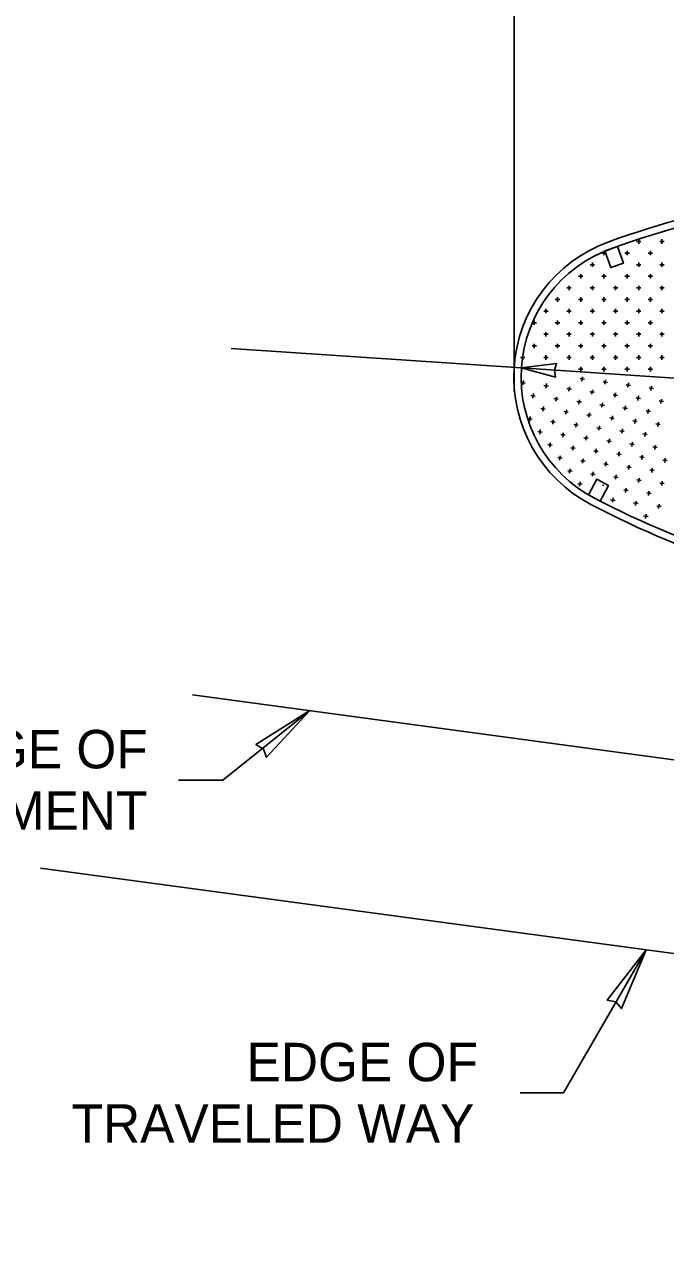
# Model space of a CAD drawing. Extents: x 1312564.5 to 1312581.5, y 1207298.4 to 1207309.4.
# Drawn here: x 1312575.116 to 1312576.451, y 1207303.021 to 1207305.558 of the extents above; entities that cross this region are included whole.
import ezdxf

# ---------------------------------------------------------------- set-up
doc = ezdxf.new("R2010")
doc.units = 0
for name, color, linetype in [('Level 15', 7, 'Continuous'), ('Level 2', 7, 'Continuous'), ('Level 20', 7, 'Continuous'), ('Level 3', 7, 'Continuous'), ('Level 4', 7, 'Continuous'), ('Level 44', 7, 'Continuous')]:
    doc.layers.add(name, color=color, linetype=linetype)

msp = doc.modelspace()

# ---------------------------------------------------------------- linework, layer by layer
at = {"layer": 'Level 15'}
for p, q in [((1312576.1506, 1207304.8426), (1312575.5468, 1207304.8833)), ((1312575.7104, 1207304.129), (1312575.5295, 1207303.9844)), ((1312575.5295, 1207303.9844), (1312575.4373, 1207303.9844)), ((1312576.4101, 1207303.6311), (1312576.2382, 1207303.3333)), ((1312576.2382, 1207303.3333), (1312576.1482, 1207303.3333))]:
    msp.add_line(p, q, dxfattribs=at)
for points in [[(1312576.1354, 1207304.7936), (1312576.1354, 1207306.1548)], [(1312576.1506, 1207304.8426), (1312579.498, 1207304.617)]]:
    msp.add_lwpolyline(points, dxfattribs=at)
for points in [[(1312576.1506, 1207304.8426), (1312576.2239, 1207304.8519), (1312576.2196, 1207304.838), (1312576.222, 1207304.8236)], [(1312575.7104, 1207304.129), (1312575.5982, 1207304.0583), (1312575.6139, 1207304.049), (1312575.6202, 1207304.0319)], [(1312576.4101, 1207303.6311), (1312576.3592, 1207303.5086), (1312576.3474, 1207303.5225), (1312576.3295, 1207303.5258)]]:
    msp.add_lwpolyline(points, close=True, dxfattribs=at)
at = {"layer": 'Level 2'}
for points in [[(1312576.3246, 1207305.0861), (1312576.3506, 1207305.0955), (1312576.3631, 1207305.0608), (1312576.3371, 1207305.0514)], [(1312576.2903, 1207304.578), (1312576.3148, 1207304.5652), (1312576.3319, 1207304.5978), (1312576.3074, 1207304.6106)]]:
    msp.add_lwpolyline(points, close=True, dxfattribs=at)
for centre, radius, start, end in [((1312577.0032, 1207303.2505), 1.9722, 89.8014, 109.8833), ((1312577.0032, 1207303.2505), 1.957, 89.83, 109.8833), ((1312576.4343, 1207304.8235), 0.2995, 109.8833, 176.1437), ((1312576.4343, 1207304.8235), 0.2843, 109.8833, 176.1437), ((1312576.4343, 1207304.8235), 0.2995, 176.1437, 242.4041), ((1312576.4343, 1207304.8235), 0.2843, 176.1437, 242.4041), ((1312577.2091, 1207306.3059), 1.9722, 242.4041, 262.486), ((1312577.2091, 1207306.3059), 1.957, 242.4041, 262.4574)]:
    msp.add_arc(centre, radius, start, end, dxfattribs=at)
at = {"layer": 'Level 3'}
msp.add_line((1312575.4659, 1207304.1621), (1312578.7245, 1207303.7208), dxfattribs=at)
at = {"layer": 'Level 4'}
for p, q in [((1312576.395, 1207305.1012), (1312576.395, 1207305.1105)), ((1312576.4433, 1207305.1012), (1312576.4433, 1207305.1105)), ((1312576.3225, 1207305.0771), (1312576.3225, 1207305.0863)), ((1312576.3709, 1207305.0771), (1312576.3709, 1207305.0863)), ((1312576.3904, 1207305.1059), (1312576.3996, 1207305.1059)), ((1312576.4192, 1207305.0771), (1312576.4192, 1207305.0863)), ((1312576.4387, 1207305.1059), (1312576.4433, 1207305.1059)), ((1312576.4433, 1207305.1059), (1312576.448, 1207305.1059)), ((1312576.2984, 1207305.0529), (1312576.2984, 1207305.0621)), ((1312576.3179, 1207305.0817), (1312576.3262, 1207305.0817)), ((1312576.3662, 1207305.0817), (1312576.3755, 1207305.0817)), ((1312576.395, 1207305.0529), (1312576.395, 1207305.0621)), ((1312576.4146, 1207305.0817), (1312576.4238, 1207305.0817)), ((1312576.4433, 1207305.0529), (1312576.4433, 1207305.0621)), ((1312576.2696, 1207305.0334), (1312576.2788, 1207305.0334)), ((1312576.2742, 1207305.0288), (1312576.2742, 1207305.038)), ((1312576.2938, 1207305.0575), (1312576.303, 1207305.0575)), ((1312576.3179, 1207305.0334), (1312576.3271, 1207305.0334)), ((1312576.3225, 1207305.0288), (1312576.3225, 1207305.038)), ((1312576.3467, 1207305.0529), (1312576.3467, 1207305.0549)), ((1312576.3662, 1207305.0334), (1312576.3755, 1207305.0334)), ((1312576.3709, 1207305.0288), (1312576.3709, 1207305.038)), ((1312576.3904, 1207305.0575), (1312576.3996, 1207305.0575)), ((1312576.4146, 1207305.0334), (1312576.4238, 1207305.0334)), ((1312576.4192, 1207305.0288), (1312576.4192, 1207305.038)), ((1312576.4387, 1207305.0575), (1312576.4433, 1207305.0575)), ((1312576.4433, 1207305.0575), (1312576.448, 1207305.0575)), ((1312576.2454, 1207305.0092), (1312576.2546, 1207305.0092)), ((1312576.25, 1207305.0046), (1312576.25, 1207305.0138)), ((1312576.2938, 1207305.0092), (1312576.303, 1207305.0092)), ((1312576.2984, 1207305.0046), (1312576.2984, 1207305.0138)), ((1312576.3421, 1207305.0092), (1312576.3513, 1207305.0092)), ((1312576.3467, 1207305.0046), (1312576.3467, 1207305.0138)), ((1312576.3904, 1207305.0092), (1312576.3996, 1207305.0092)), ((1312576.395, 1207305.0046), (1312576.395, 1207305.0138)), ((1312576.4387, 1207305.0092), (1312576.4433, 1207305.0092)), ((1312576.4433, 1207305.0046), (1312576.4433, 1207305.0138)), ((1312576.4433, 1207305.0092), (1312576.448, 1207305.0092)), ((1312576.1821, 1207304.985), (1312576.1821, 1207304.985)), ((1312576.2213, 1207304.985), (1312576.2305, 1207304.985)), ((1312576.2259, 1207304.9804), (1312576.2259, 1207304.9896)), ((1312576.2696, 1207304.985), (1312576.2788, 1207304.985)), ((1312576.2742, 1207304.9804), (1312576.2742, 1207304.9896)), ((1312576.3179, 1207304.985), (1312576.3271, 1207304.985)), ((1312576.3225, 1207304.9804), (1312576.3225, 1207304.9896)), ((1312576.3662, 1207304.985), (1312576.3755, 1207304.985)), ((1312576.3709, 1207304.9804), (1312576.3709, 1207304.9896)), ((1312576.4146, 1207304.985), (1312576.4238, 1207304.985)), ((1312576.4192, 1207304.9804), (1312576.4192, 1207304.9896)), ((1312576.1971, 1207304.9609), (1312576.2063, 1207304.9609)), ((1312576.2017, 1207304.9609), (1312576.2017, 1207304.9655)), ((1312576.2017, 1207304.9563), (1312576.2017, 1207304.9609)), ((1312576.2454, 1207304.9609), (1312576.2546, 1207304.9609)), ((1312576.25, 1207304.9609), (1312576.25, 1207304.9655)), ((1312576.25, 1207304.9563), (1312576.25, 1207304.9609)), ((1312576.2938, 1207304.9609), (1312576.303, 1207304.9609)), ((1312576.2984, 1207304.9609), (1312576.2984, 1207304.9655)), ((1312576.2984, 1207304.9563), (1312576.2984, 1207304.9609)), ((1312576.3421, 1207304.9609), (1312576.3513, 1207304.9609)), ((1312576.3467, 1207304.9609), (1312576.3467, 1207304.9655)), ((1312576.3467, 1207304.9563), (1312576.3467, 1207304.9609)), ((1312576.3904, 1207304.9609), (1312576.3996, 1207304.9609)), ((1312576.395, 1207304.9609), (1312576.395, 1207304.9655)), ((1312576.395, 1207304.9563), (1312576.395, 1207304.9609)), ((1312576.4387, 1207304.9609), (1312576.4433, 1207304.9609)), ((1312576.4433, 1207304.9609), (1312576.4433, 1207304.9655)), ((1312576.4433, 1207304.9563), (1312576.4433, 1207304.9609)), ((1312576.4433, 1207304.9609), (1312576.448, 1207304.9609)), ((1312576.1729, 1207304.9367), (1312576.1821, 1207304.9367)), ((1312576.1775, 1207304.9321), (1312576.1775, 1207304.9413)), ((1312576.2213, 1207304.9367), (1312576.2305, 1207304.9367)), ((1312576.2259, 1207304.9321), (1312576.2259, 1207304.9413)), ((1312576.2696, 1207304.9367), (1312576.2788, 1207304.9367)), ((1312576.2742, 1207304.9321), (1312576.2742, 1207304.9413)), ((1312576.3179, 1207304.9367), (1312576.3271, 1207304.9367)), ((1312576.3225, 1207304.9321), (1312576.3225, 1207304.9413)), ((1312576.3662, 1207304.9367), (1312576.3755, 1207304.9367)), ((1312576.3709, 1207304.9321), (1312576.3709, 1207304.9413)), ((1312576.4146, 1207304.9367), (1312576.4238, 1207304.9367)), ((1312576.4192, 1207304.9321), (1312576.4192, 1207304.9413)), ((1312576.1971, 1207304.9125), (1312576.2063, 1207304.9125)), ((1312576.2017, 1207304.9079), (1312576.2017, 1207304.9172)), ((1312576.2454, 1207304.9125), (1312576.2546, 1207304.9125)), ((1312576.25, 1207304.9079), (1312576.25, 1207304.9172)), ((1312576.2938, 1207304.9125), (1312576.303, 1207304.9125)), ((1312576.2984, 1207304.9079), (1312576.2984, 1207304.9172)), ((1312576.3421, 1207304.9125), (1312576.3513, 1207304.9125)), ((1312576.3467, 1207304.9079), (1312576.3467, 1207304.9172)), ((1312576.3904, 1207304.9125), (1312576.3996, 1207304.9125)), ((1312576.395, 1207304.9079), (1312576.395, 1207304.9172)), ((1312576.4387, 1207304.9125), (1312576.4433, 1207304.9125)), ((1312576.4433, 1207304.9079), (1312576.4433, 1207304.9172)), ((1312576.4433, 1207304.9125), (1312576.448, 1207304.9125)), ((1312576.1729, 1207304.8884), (1312576.1821, 1207304.8884)), ((1312576.1775, 1207304.8838), (1312576.1775, 1207304.893)), ((1312576.2213, 1207304.8884), (1312576.2305, 1207304.8884)), ((1312576.2259, 1207304.8838), (1312576.2259, 1207304.893)), ((1312576.2696, 1207304.8884), (1312576.2788, 1207304.8884)), ((1312576.2742, 1207304.8838), (1312576.2742, 1207304.893)), ((1312576.3179, 1207304.8884), (1312576.3271, 1207304.8884)), ((1312576.3225, 1207304.8838), (1312576.3225, 1207304.893)), ((1312576.3662, 1207304.8884), (1312576.3755, 1207304.8884)), ((1312576.3709, 1207304.8838), (1312576.3709, 1207304.893)), ((1312576.4146, 1207304.8884), (1312576.4238, 1207304.8884)), ((1312576.4192, 1207304.8838), (1312576.4192, 1207304.893)), ((1312576.1488, 1207304.8642), (1312576.1534, 1207304.8642)), ((1312576.1534, 1207304.8596), (1312576.1534, 1207304.8688)), ((1312576.1534, 1207304.8642), (1312576.158, 1207304.8642)), ((1312576.1971, 1207304.8642), (1312576.2063, 1207304.8642)), ((1312576.2017, 1207304.8596), (1312576.2017, 1207304.8688)), ((1312576.2454, 1207304.8642), (1312576.2546, 1207304.8642)), ((1312576.25, 1207304.8596), (1312576.25, 1207304.8688)), ((1312576.2938, 1207304.8642), (1312576.303, 1207304.8642)), ((1312576.2984, 1207304.8596), (1312576.2984, 1207304.8688)), ((1312576.3421, 1207304.8642), (1312576.3513, 1207304.8642)), ((1312576.3467, 1207304.8596), (1312576.3467, 1207304.8688)), ((1312576.3904, 1207304.8642), (1312576.3996, 1207304.8642)), ((1312576.395, 1207304.8596), (1312576.395, 1207304.8688)), ((1312576.4387, 1207304.8642), (1312576.4433, 1207304.8642)), ((1312576.4433, 1207304.8596), (1312576.4433, 1207304.8688)), ((1312576.4433, 1207304.8642), (1312576.448, 1207304.8642)), ((1312576.2696, 1207304.8401), (1312576.2788, 1207304.8401)), ((1312576.2742, 1207304.8354), (1312576.2742, 1207304.8447)), ((1312576.3179, 1207304.8401), (1312576.3271, 1207304.8401)), ((1312576.3225, 1207304.8354), (1312576.3225, 1207304.8447)), ((1312576.3662, 1207304.8401), (1312576.3755, 1207304.8401)), ((1312576.3709, 1207304.8354), (1312576.3709, 1207304.8447)), ((1312576.4146, 1207304.8401), (1312576.4238, 1207304.8401)), ((1312576.4192, 1207304.8354), (1312576.4192, 1207304.8447)), ((1312576.1498, 1207304.8122), (1312576.1544, 1207304.8116)), ((1312576.155, 1207304.8162), (1312576.1538, 1207304.8071)), ((1312576.1544, 1207304.8116), (1312576.1589, 1207304.811)), ((1312576.1977, 1207304.8058), (1312576.2068, 1207304.8046)), ((1312576.2029, 1207304.8098), (1312576.2017, 1207304.8007)), ((1312576.2728, 1207304.8202), (1312576.2819, 1207304.8189)), ((1312576.2779, 1207304.8241), (1312576.2767, 1207304.815)), ((1312576.3207, 1207304.8137), (1312576.3298, 1207304.8125)), ((1312576.3258, 1207304.8177), (1312576.3246, 1207304.8086)), ((1312576.3686, 1207304.8073), (1312576.3777, 1207304.8061)), ((1312576.3737, 1207304.8113), (1312576.3725, 1207304.8022)), ((1312576.4216, 1207304.8049), (1312576.4204, 1207304.7957)), ((1312576.1706, 1207304.7851), (1312576.1797, 1207304.7839)), ((1312576.1757, 1207304.789), (1312576.1745, 1207304.7799)), ((1312576.2236, 1207304.7826), (1312576.2224, 1207304.7735)), ((1312576.2456, 1207304.7994), (1312576.2547, 1207304.7982)), ((1312576.2508, 1207304.8034), (1312576.2496, 1207304.7942)), ((1312576.2935, 1207304.793), (1312576.3026, 1207304.7918)), ((1312576.2987, 1207304.797), (1312576.2975, 1207304.7878)), ((1312576.3414, 1207304.7866), (1312576.3505, 1207304.7854)), ((1312576.3466, 1207304.7905), (1312576.3454, 1207304.7814)), ((1312576.3893, 1207304.7802), (1312576.3984, 1207304.779)), ((1312576.3945, 1207304.7841), (1312576.3933, 1207304.775)), ((1312576.4165, 1207304.8009), (1312576.4256, 1207304.7997)), ((1312576.1913, 1207304.7579), (1312576.2004, 1207304.7567)), ((1312576.1965, 1207304.7619), (1312576.1953, 1207304.7528)), ((1312576.2185, 1207304.7787), (1312576.2276, 1207304.7774)), ((1312576.2444, 1207304.7555), (1312576.2432, 1207304.7463)), ((1312576.2664, 1207304.7723), (1312576.2755, 1207304.771)), ((1312576.2715, 1207304.7762), (1312576.2703, 1207304.7671)), ((1312576.3143, 1207304.7658), (1312576.3234, 1207304.7646)), ((1312576.3194, 1207304.7698), (1312576.3182, 1207304.7607)), ((1312576.3622, 1207304.7594), (1312576.3713, 1207304.7582)), ((1312576.3673, 1207304.7634), (1312576.3661, 1207304.7543)), ((1312576.4152, 1207304.757), (1312576.414, 1207304.7478)), ((1312576.4372, 1207304.7738), (1312576.4418, 1207304.7731)), ((1312576.4424, 1207304.7777), (1312576.4412, 1207304.7686)), ((1312576.4418, 1207304.7731), (1312576.4463, 1207304.7725)), ((1312576.1641, 1207304.7372), (1312576.1733, 1207304.736)), ((1312576.1693, 1207304.7411), (1312576.1681, 1207304.732)), ((1312576.212, 1207304.7308), (1312576.2212, 1207304.7295)), ((1312576.2172, 1207304.7347), (1312576.216, 1207304.7256)), ((1312576.2392, 1207304.7515), (1312576.2483, 1207304.7503)), ((1312576.2871, 1207304.7451), (1312576.2962, 1207304.7439)), ((1312576.2923, 1207304.7491), (1312576.2911, 1207304.7399)), ((1312576.335, 1207304.7387), (1312576.3441, 1207304.7375)), ((1312576.3402, 1207304.7426), (1312576.339, 1207304.7335)), ((1312576.3829, 1207304.7323), (1312576.392, 1207304.7311)), ((1312576.3881, 1207304.7362), (1312576.3869, 1207304.7271)), ((1312576.4101, 1207304.753), (1312576.4192, 1207304.7518)), ((1312576.436, 1207304.7298), (1312576.4348, 1207304.7207)), ((1312576.1849, 1207304.71), (1312576.194, 1207304.7088)), ((1312576.1895, 1207304.7094), (1312576.1888, 1207304.7049)), ((1312576.1901, 1207304.714), (1312576.1895, 1207304.7094)), ((1312576.2328, 1207304.7036), (1312576.2419, 1207304.7024)), ((1312576.238, 1207304.7076), (1312576.2374, 1207304.703)), ((1312576.2599, 1207304.7244), (1312576.2691, 1207304.7231)), ((1312576.2651, 1207304.7283), (1312576.2639, 1207304.7192)), ((1312576.3078, 1207304.7179), (1312576.317, 1207304.7167)), ((1312576.313, 1207304.7219), (1312576.3118, 1207304.7128)), ((1312576.3557, 1207304.7115), (1312576.3649, 1207304.7103)), ((1312576.3609, 1207304.7155), (1312576.3597, 1207304.7064)), ((1312576.4036, 1207304.7051), (1312576.4128, 1207304.7039)), ((1312576.4088, 1207304.7091), (1312576.4076, 1207304.6999)), ((1312576.4308, 1207304.7259), (1312576.4354, 1207304.7252)), ((1312576.4354, 1207304.7252), (1312576.4399, 1207304.7246)), ((1312576.1668, 1207304.6881), (1312576.1669, 1207304.6881)), ((1312576.2056, 1207304.6829), (1312576.2148, 1207304.6816)), ((1312576.2108, 1207304.6868), (1312576.2096, 1207304.6777)), ((1312576.2374, 1207304.703), (1312576.2367, 1207304.6984)), ((1312576.2587, 1207304.6804), (1312576.2575, 1207304.6713)), ((1312576.2807, 1207304.6972), (1312576.2898, 1207304.696)), ((1312576.2853, 1207304.6966), (1312576.2846, 1207304.692)), ((1312576.2859, 1207304.7012), (1312576.2853, 1207304.6966)), ((1312576.3286, 1207304.6908), (1312576.3377, 1207304.6896)), ((1312576.3332, 1207304.6902), (1312576.3325, 1207304.6856)), ((1312576.3338, 1207304.6947), (1312576.3332, 1207304.6902)), ((1312576.3765, 1207304.6844), (1312576.3856, 1207304.6831)), ((1312576.3811, 1207304.6838), (1312576.3804, 1207304.6792)), ((1312576.3817, 1207304.6883), (1312576.3811, 1207304.6838)), ((1312576.4244, 1207304.678), (1312576.429, 1207304.6773)), ((1312576.4296, 1207304.6819), (1312576.429, 1207304.6773)), ((1312576.2264, 1207304.6557), (1312576.2355, 1207304.6545)), ((1312576.2315, 1207304.6597), (1312576.2303, 1207304.6505)), ((1312576.2535, 1207304.6765), (1312576.2627, 1207304.6752)), ((1312576.2794, 1207304.6533), (1312576.2782, 1207304.6441)), ((1312576.3014, 1207304.67), (1312576.3106, 1207304.6688)), ((1312576.3066, 1207304.674), (1312576.3054, 1207304.6649)), ((1312576.3493, 1207304.6636), (1312576.3585, 1207304.6624)), ((1312576.3545, 1207304.6676), (1312576.3533, 1207304.6585)), ((1312576.3972, 1207304.6572), (1312576.4064, 1207304.656)), ((1312576.4024, 1207304.6612), (1312576.4012, 1207304.652)), ((1312576.429, 1207304.6773), (1312576.4283, 1207304.6728)), ((1312576.429, 1207304.6773), (1312576.4335, 1207304.6767)), ((1312576.4503, 1207304.6548), (1312576.4491, 1207304.6456)), ((1312576.2471, 1207304.6286), (1312576.2562, 1207304.6273)), ((1312576.2523, 1207304.6325), (1312576.2511, 1207304.6234)), ((1312576.2743, 1207304.6493), (1312576.2834, 1207304.6481)), ((1312576.3222, 1207304.6429), (1312576.3313, 1207304.6417)), ((1312576.3273, 1207304.6468), (1312576.3261, 1207304.6377)), ((1312576.3701, 1207304.6365), (1312576.3792, 1207304.6352)), ((1312576.3752, 1207304.6404), (1312576.374, 1207304.6313)), ((1312576.418, 1207304.6301), (1312576.4225, 1207304.6294)), ((1312576.4231, 1207304.634), (1312576.4219, 1207304.6249)), ((1312576.4225, 1207304.6294), (1312576.4271, 1207304.6288)), ((1312576.4451, 1207304.6508), (1312576.4543, 1207304.6496)), ((1312576.273, 1207304.6054), (1312576.2718, 1207304.5962)), ((1312576.295, 1207304.6221), (1312576.3041, 1207304.6209)), ((1312576.3002, 1207304.6261), (1312576.299, 1207304.617)), ((1312576.3429, 1207304.6157), (1312576.352, 1207304.6145)), ((1312576.3481, 1207304.6197), (1312576.3469, 1207304.6106)), ((1312576.3908, 1207304.6093), (1312576.3999, 1207304.6081)), ((1312576.396, 1207304.6133), (1312576.3948, 1207304.6041)), ((1312576.4387, 1207304.6029), (1312576.4478, 1207304.6017)), ((1312576.4439, 1207304.6069), (1312576.4427, 1207304.5977)), ((1312576.2679, 1207304.6014), (1312576.277, 1207304.6002)), ((1312576.3209, 1207304.5989), (1312576.3207, 1207304.597)), ((1312576.3637, 1207304.5886), (1312576.3728, 1207304.5873)), ((1312576.3688, 1207304.5925), (1312576.3676, 1207304.5834)), ((1312576.4116, 1207304.5822), (1312576.4161, 1207304.5815)), ((1312576.4167, 1207304.5861), (1312576.4155, 1207304.577)), ((1312576.4161, 1207304.5815), (1312576.4207, 1207304.5809)), ((1312576.3365, 1207304.5678), (1312576.3456, 1207304.5666)), ((1312576.3417, 1207304.5718), (1312576.3405, 1207304.5627)), ((1312576.3844, 1207304.5614), (1312576.3935, 1207304.5602)), ((1312576.3896, 1207304.5654), (1312576.3884, 1207304.5562)), ((1312576.4323, 1207304.555), (1312576.4414, 1207304.5538)), ((1312576.4375, 1207304.559), (1312576.4363, 1207304.5498)), ((1312576.4051, 1207304.5343), (1312576.4097, 1207304.5336)), ((1312576.4103, 1207304.5382), (1312576.4091, 1207304.5291)), ((1312576.4097, 1207304.5336), (1312576.4143, 1207304.533))]:
    msp.add_line(p, q, dxfattribs=at)
at = {"layer": 'Level 44'}
msp.add_line((1312580.938, 1207303.0213), (1312575.1495, 1207303.8008), dxfattribs=at)

# ---------------------------------------------------------------- texts
at = {"layer": 'Level 20'}
for s, p in [('EDGE OF', (1312574.8915, 1207304.0088)), (' PAVEMENT', (1312574.7541, 1207303.8808)), ('EDGE OF', (1312575.5788, 1207303.3573)), (' TRAVELED WAY', (1312575.1849, 1207303.2293))]:
    msp.add_text(s, height=0.08, dxfattribs=at).set_placement(p)

doc.saveas('drawing.dxf')
